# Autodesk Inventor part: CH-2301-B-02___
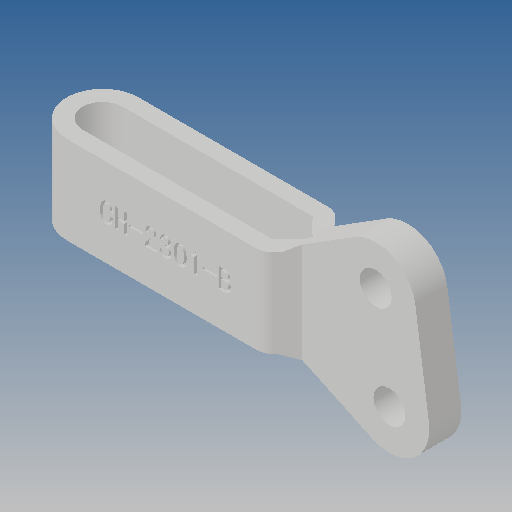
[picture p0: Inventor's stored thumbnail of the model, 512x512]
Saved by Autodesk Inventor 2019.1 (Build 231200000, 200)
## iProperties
Created: 2012-09
Part Number: CH-2301-B-02___
Material: Ogólny
Document SubType Name: Modeling
Designer: CADENGINEERING4
Density: 1 g/cm^3
Appearance: Domyślna
Author: CADENGINEERING4
Revision Number: ÈÎºÎ
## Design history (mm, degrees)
feature "NONE"
node "Bryła1"
